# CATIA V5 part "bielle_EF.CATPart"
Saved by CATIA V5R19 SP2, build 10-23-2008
Part number: bielle_EF
Publications: "L_EF"
Bounding box of the stored display mesh (mm): x -160 to 160, y -10 to 10, z 0 to 10
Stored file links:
  D:\Dropbox\IAO_2011\MMS_GR2\IAO_2011_1521_alefevre\IAO_2011_1521_alefevre\bielle_EF.CATPart
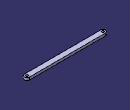
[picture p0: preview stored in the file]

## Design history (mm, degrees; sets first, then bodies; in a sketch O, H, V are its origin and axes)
Parameters
  L_EF = 300 mm
Body1 (main body)
  Sketch1 on xy-plane, origin (0, 0, 0), H (1, 0, 0), V (0, 1, 0)
    construction line L1 (-150, 0) -> (150, 0)
    point P1 (-150, 0)
    point P2 (150, 0)
    line L2 (-150, 10) -> (150, 10)
    line L3 (150, -10) -> (-150, -10)
    arc A1 centre (150, 0) radius 10 from (150, 10) to (150, -10) cw
    arc A2 centre (-150, 0) radius 10 from (-150, -10) to (-150, 10) cw
    circle A3 centre (150, 0) radius 5
    circle A4 centre (-150, 0) radius 5
    distance L1 L2 = 10
    radius A3 = 5
    radius A4 = 5
    distance P2 V = 150 {= L_EF /2}
    distance P2 P1 = 300 {= L_EF}
    coincidence: P1 H
    horizontal: L1 H
    tangency: A1 L2, A2 L2, A1 L3, A2 L3
  Pad1: profile Sketch1, direction (0, 0, 1), length 10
